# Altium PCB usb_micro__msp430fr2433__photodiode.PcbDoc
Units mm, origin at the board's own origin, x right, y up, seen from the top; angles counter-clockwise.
Board outline 56 x 30 mm, 2 copper layers (Top, Bottom), stack 0 mm thick; 25 components, 16 nets, 114 pads, 40 vias.
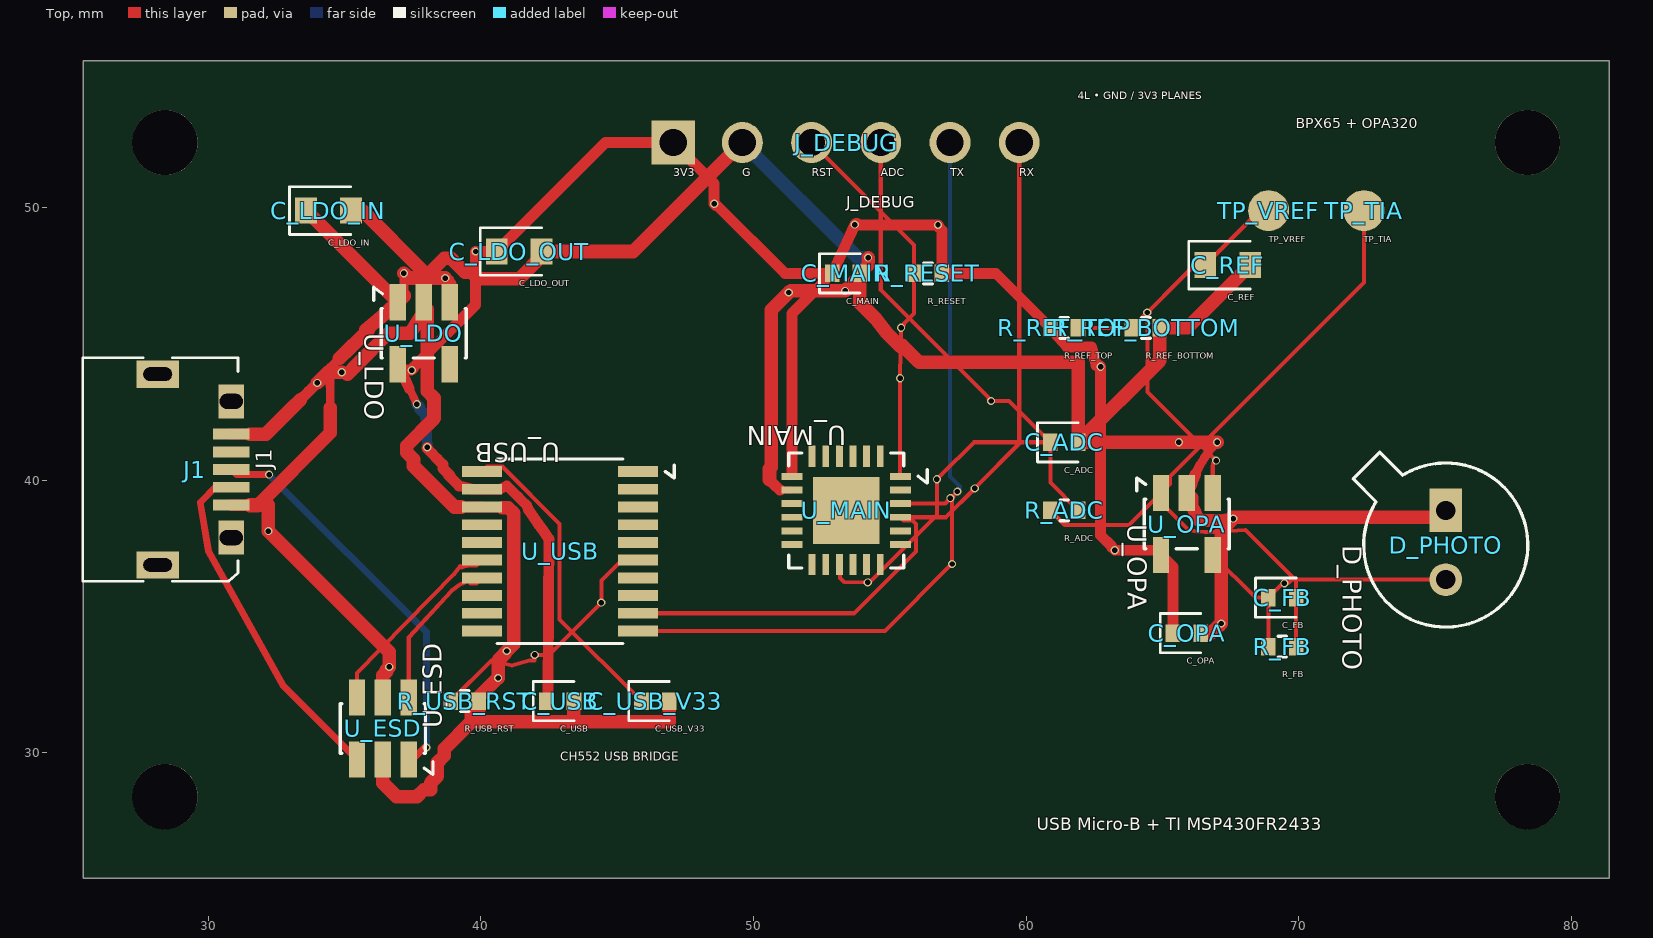
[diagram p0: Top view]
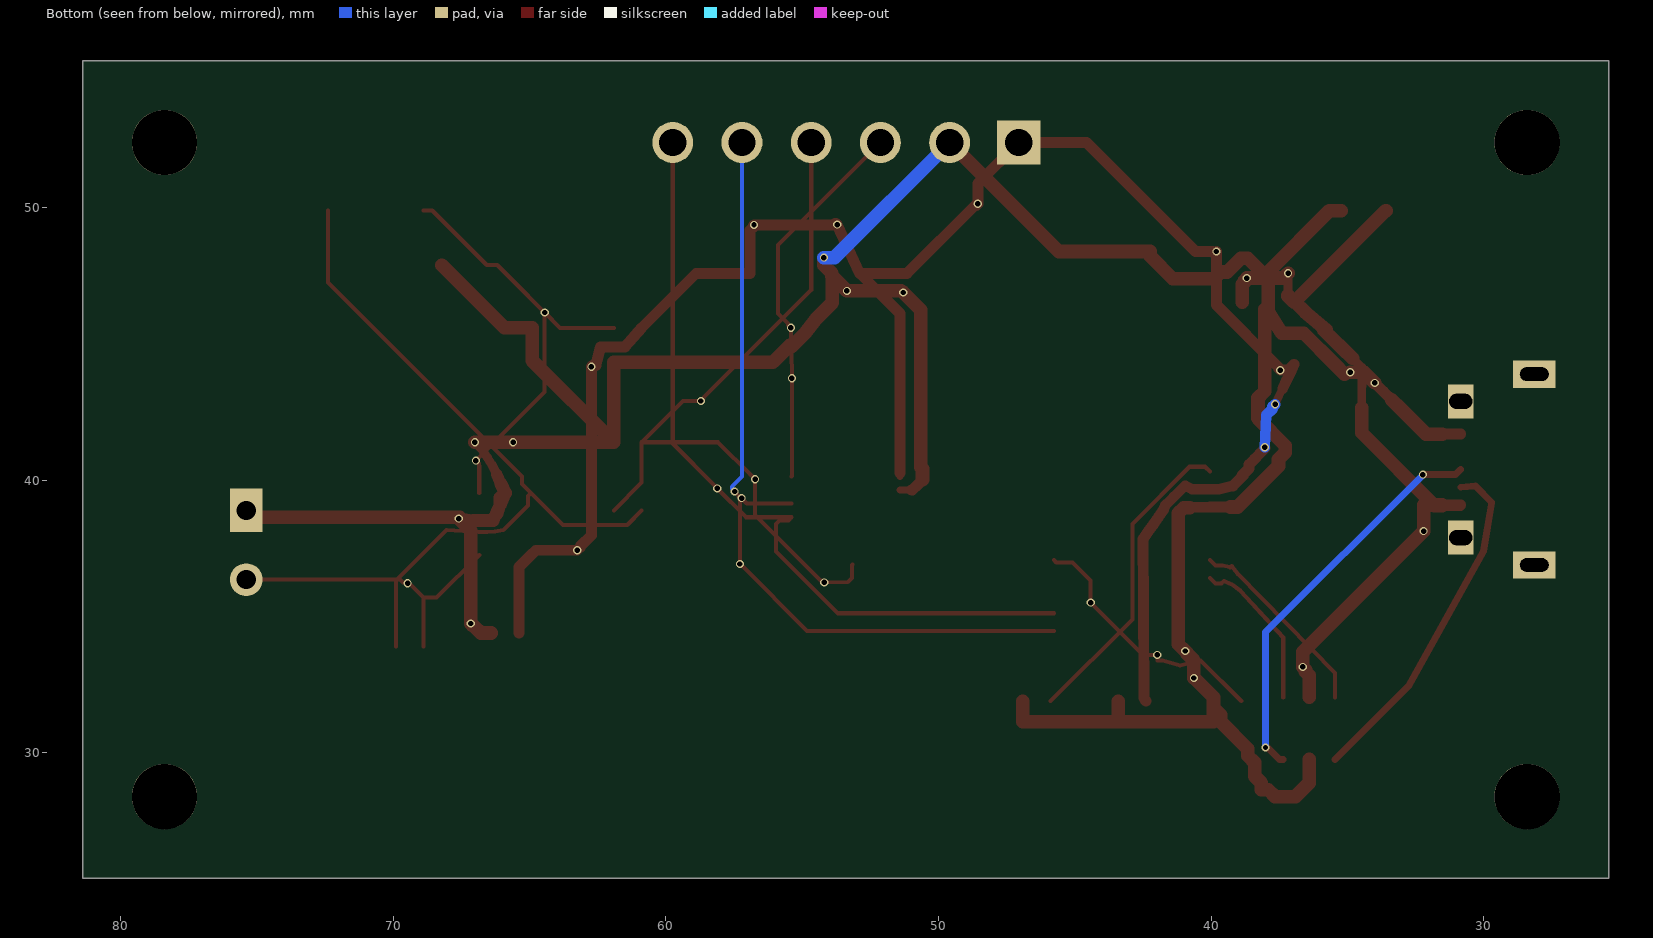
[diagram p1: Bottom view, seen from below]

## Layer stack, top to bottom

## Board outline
25.4,55.4 81.4,55.4 81.4,25.4 25.4,25.4

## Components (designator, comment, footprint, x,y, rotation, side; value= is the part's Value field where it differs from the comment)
C_ADC "" TSCIRCUIT-1.5600x0.6400mm 61.4,41.4 r0 top
C_FB "" TSCIRCUIT-1.5600x0.6400mm 69.4,35.7 r0 top
C_LDO_IN "" TSCIRCUIT-2.4500x0.9500mm 34.4,49.9 r0 top
C_LDO_OUT "" TSCIRCUIT-2.4500x0.9500mm 41.4,48.4 r0 top
C_MAIN "" TSCIRCUIT-1.5600x0.6400mm 53.4,47.6 r0 top
C_OPA "" TSCIRCUIT-1.5600x0.6400mm 65.9,34.4 r0 top
C_REF "" TSCIRCUIT-2.4500x0.9500mm 67.4,47.9 r0 top
C_USB "" TSCIRCUIT-1.5600x0.6400mm 42.9,31.9 r0 top
C_USB_V33 "" TSCIRCUIT-1.5600x0.6400mm 46.4,31.9 r0 top
D_PHOTO "" TSCIRCUIT-1.2000x3.9400mm 75.4,37.73 r270 top
J1 "" TSCIRCUIT-4.1500x8mm 29.437,40.4 r90 top
J_DEBUG "" TSCIRCUIT-14.2000x1.5000mm 53.4,52.4 r0 top
R_ADC "" TSCIRCUIT-1.5600x0.6400mm 61.4,38.9 r0 top
R_FB "" TSCIRCUIT-1.5600x0.6400mm 69.4,33.9 r0 top
R_REF_BOTTOM "" TSCIRCUIT-1.5600x0.6400mm 64.4,45.6 r0 top
R_REF_TOP "" TSCIRCUIT-1.5600x0.6400mm 61.4,45.6 r0 top
R_RESET "" TSCIRCUIT-1.5600x0.6400mm 56.4,47.6 r0 top
R_USB_RST "" TSCIRCUIT-1.5600x0.6400mm 39.4,31.9 r0 top
TP_TIA "" TSCIRCUIT-1.5000x1.5000mm 72.4,49.9 r0 top
TP_VREF "" TSCIRCUIT-1.5000x1.5000mm 68.9,49.9 r0 top
U_ESD "" TSCIRCUIT-2.5000x3.6000mm#1 36.4,30.9 r90 top
U_LDO "" TSCIRCUIT-2.5000x3.6000mm#2 37.9,45.4 r270 top
U_MAIN "" TSCIRCUIT-4.7500x4.7500mm 53.4,38.9 r180 top
U_OPA "" TSCIRCUIT-2.5000x3.6000mm#2 65.9,38.4 r270 top
U_USB "" TSCIRCUIT-7.2000x6.2500mm 42.9,37.4 r180 top

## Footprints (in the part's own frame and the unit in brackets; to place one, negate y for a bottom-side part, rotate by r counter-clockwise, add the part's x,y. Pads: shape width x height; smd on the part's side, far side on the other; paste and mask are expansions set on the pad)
TSCIRCUIT-1.2000x3.9400mm [mm]
  rect 1.6x1.2 hole 0.7: 1(-1.17,0)
  round 1.2 hole 0.7: 2(1.37,0)
  silkscreen extent -3.3,-3.4 3.11,3.01
TSCIRCUIT-1.5000x1.5000mm [mm]
  round 1.5 smd: 1(0,0)
TSCIRCUIT-1.5600x0.6400mm [mm]
  rect 0.54x0.64 smd: 1(-0.51,0) 2(0.51,0)
  silkscreen extent -0.98,-0.72 0.51,0.72
TSCIRCUIT-2.4500x0.9500mm [mm]
  rect 0.8x0.95 smd: 1(-0.825,0) 2(0.825,0)
  silkscreen extent -1.43,-0.87 0.82,0.87
TSCIRCUIT-2.5000x3.6000mm#1 [mm]
  rect 1.325x0.6 smd: 1(-1.137,-0.95) 2(-1.137,0) 3(-1.137,0.95) 4(1.138,0.95) 5(1.138,0) 6(1.138,-0.95)
  silkscreen extent -1.69,-1.84 0.91,1.56
TSCIRCUIT-2.5000x3.6000mm#2 [mm]
  rect 1.325x0.6 smd: 1(-1.137,-0.95) 2(-1.137,0) 3(-1.137,0.95) 4(1.138,0.95) 5(1.138,-0.95)
  silkscreen extent -1.69,-1.84 0.91,1.56
TSCIRCUIT-4.1500x8mm [mm]
  rect 0.4x1.35 smd: 1(-1.301,-1.4) 2(-0.65,-1.4) 3(0,-1.4) 4(0.65,-1.4) 5(1.3,-1.4)
  rect 1.25x0.95 hole 0.55 slot 0.85 at 90 deg: 6(2.5,-1.4) 7(-2.5,-1.4)
  rect 1x1.55 hole 0.5 slot 1.05 at 90 deg: 8(-3.5,1.3) 9(3.5,1.3)
  silkscreen extent -4.1,-1.65 4.1,4.05
TSCIRCUIT-4.7500x4.7500mm [mm]
  rect 0.775x0.25 smd: 1(-1.987,-1.25) 2(-1.987,-0.75) 3(-1.987,-0.25) 4(-1.987,0.25) 5(-1.987,0.75) 6(-1.987,1.25) 13(1.987,1.25) 14(1.987,0.75) 15(1.987,0.25) 16(1.987,-0.25) 17(1.987,-0.75) 18(1.987,-1.25)
  rect 0.25x0.775 smd: 7(-1.25,1.988) 8(-0.75,1.988) 9(-0.25,1.988) 10(0.25,1.988) 11(0.75,1.988) 12(1.25,1.988) 19(1.25,-1.987) 20(0.75,-1.987) 21(0.25,-1.987) 22(-0.25,-1.987) 23(-0.75,-1.987) 24(-1.25,-1.987)
  rect 2.45x2.45 smd: 25(0,0)
  silkscreen extent -2.97,-2.11 2.11,2.11
TSCIRCUIT-7.2000x6.2500mm [mm]
  rect 1.475x0.4 smd: 1(-2.862,-2.925) 2(-2.862,-2.275) 3(-2.862,-1.625) 4(-2.862,-0.975) 5(-2.862,-0.325) 6(-2.862,0.325) 7(-2.862,0.975) 8(-2.862,1.625) 9(-2.862,2.275) 10(-2.862,2.925) 11(2.863,2.925) 12(2.863,2.275) 13(2.863,1.625) 14(2.863,0.975) 15(2.863,0.325) 16(2.863,-0.325) 17(2.863,-0.975) 18(2.863,-1.625) 19(2.863,-2.275) 20(2.863,-2.925)
  silkscreen extent -4.19,-3.39 2.31,3.38
TSCIRCUIT-14.2000x1.5000mm [mm]
  rect 1.6x1.6 hole 1: 1(-6.35,0)
  round 1.5 hole 1: 2(-3.81,0) 3(-1.27,0) 4(1.27,0) 5(3.81,0) 6(6.35,0)

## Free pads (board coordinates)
  round 2.4 hole 2.4 unplated: NPTH-1(28.4,28.4) NPTH-2(78.4,52.4) NPTH-3(78.4,28.4) NPTH-4(28.4,52.4)

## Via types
v1: diameter 0.3, hole 0.2, Top to Bottom, 40 vias

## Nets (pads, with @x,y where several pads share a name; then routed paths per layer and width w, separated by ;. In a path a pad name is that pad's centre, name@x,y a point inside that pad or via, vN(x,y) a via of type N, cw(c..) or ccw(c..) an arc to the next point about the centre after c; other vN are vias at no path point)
ADC_IN: C_ADC.1 J_DEBUG.4 R_ADC.2 U_MAIN.10 | length 28.1
  Top w0.15: U_MAIN.10 53.173,36.889 53.173,36.424 53.328,36.268 v1(54.189,36.26) 54.248,36.327 54.329,36.327 56.728,38.725 v1(56.728,40.041) 56.887,40.2 58.087,41.4 C_ADC.1 ; J_DEBUG.4 54.67,46.984 58.618,43.036 58.618,43.013 v1(58.716,42.915) 59.375,42.915 C_ADC.1 ; R_ADC.2 60.89,39.92 C_ADC.1
GND: C_ADC.2 C_LDO_IN.2 C_LDO_OUT.2 C_MAIN.2 C_OPA.2 C_REF.2 C_USB.2 C_USB_V33.2 D_PHOTO.1 J1.5 J_DEBUG.2 R_REF_BOTTOM.2 R_USB_RST.2 U_ESD.2 U_LDO.2 U_MAIN.17 U_OPA.2 U_USB.18 | length 130.7
  Top w0.25: U_MAIN.17@51.025,39.65 U_MAIN.17
  Top w0.325: v1(34.891,43.969) 35.1,43.9 ; 66.369,40.556 66.552,40.841 66.734,41.125 v1(67.013,41.401)
  Top w0.35: 66.212,40.217 66.369,40.556
  Top w0.375: 50.962,39.65 51.025,39.65
  Top w0.4: J1.5 31.262,41.7 31.513,41.7 ; 33.364,42.952 33.677,43.265 v1(33.99,43.578) ; U_USB.18@39.3,39.025 U_USB.18 U_USB.18@40.775,39.001 ; 50.588,40.025 50.775,39.837 50.962,39.65
  Top w0.425: U_OPA.2@66.056,39.877 66.212,40.217
  Top w0.437: 66.744,38.541 67.072,38.541 67.336,38.57 v1(67.6,38.6) ; 66.9,38.525 67.291,38.541 v1@67.567,38.645
  Top w0.45: U_OPA.2@66.056,39.188 66.212,38.837 66.338,38.525 66.619,38.525 66.9,38.525 ; U_OPA.2@66.076,39.121 66.197,38.759 66.416,38.541 66.744,38.541
  Top w0.475: U_OPA.2@66.056,39.188 U_OPA.2 U_OPA.2@66.056,39.877
  Top w0.5: 31.513,41.7 31.687,41.7 32.112,41.7 32.425,42.013 32.738,42.326 33.051,42.639 33.364,42.952 ; v1(33.99,43.578) 34.381,43.969 v1(34.891,43.969) ; 35.1,43.9 35.45,44.25 36.6,45.4 37.4,45.4 37.9,46.186 U_LDO.2 ; C_LDO_IN.2 35.65,49.9 37.9,47.65 U_LDO.2 ; U_ESD.2 36.4,28.9 36.9,28.4 37.65,28.4 37.9,28.65 38.15,28.65 38.15,28.9 38.4,29.15 38.4,29.65 38.65,29.9 38.65,30.15 39.65,31.15 39.65,31.4 39.91,31.66 R_USB_RST.2 ; U_USB.18@39.3,39.025 39.025,39.025 37.525,40.525 37.525,40.775 37.275,41.025 37.275,41.275 38.275,42.275 38.275,43.025 38.025,43.275 38.025,46.275 37.9,46.4 U_LDO.2 ; 40.775,39.001 40.8,39 41,39 41.2,38.8 41.2,33.993 v1(40.948,33.741) 40.88,33.673 40.88,33.644 40.628,33.392 40.628,33.071 v1(40.628,32.75) 40.527,32.649 40.516,32.649 40.213,32.346 39.91,32.043 R_USB_RST.2 ; C_USB_V33.2 46.91,31.15 43.41,31.15 ; J_DEBUG.2 45.59,48.4 C_LDO_OUT.2 42.225,48.225 41.4,47.4 39.9,47.4 39.65,47.65 39.4,47.65 38.9,48.15 38.65,48.15 37.9,47.4 U_LDO.2 ; 50.588,40.025 50.588,40.421 50.651,40.485 50.651,46.255 v1(51.292,46.896) 51.342,46.946 51.365,46.946 51.374,46.955 51.87,46.955 52.367,46.955 52.863,46.955 v1(53.36,46.955) 53.91,47.505 C_MAIN.2 ; v1(54.206,48.177) 54.206,47.896 C_MAIN.2 ; U_OPA.2 66.076,39.362 U_OPA.2@66.076,39.121 ; C_OPA.2 66.788,34.4 67.051,34.663 67.078,34.663 v1(67.165,34.75) 67.165,38.165 v1(67.6,38.6) ; v1(67.013,41.401) 67.011,41.4 v1(65.609,41.4) 65.41,41.4 64.91,41.4 64.41,41.4 63.91,41.4 63.41,41.4 62.91,41.4 62.41,41.4 C_ADC.2 ; v1@67.567,38.645 68.041,38.645 68.514,38.645 68.988,38.645 69.461,38.645 69.935,38.645 70.409,38.645 70.882,38.645 71.356,38.645 71.83,38.645 72.303,38.645 72.777,38.645 73.25,38.645 73.724,38.645 74.198,38.645 74.671,38.645 75.145,38.645 D_PHOTO.1 ; C_REF.2 65.925,45.6 R_REF_BOTTOM.2 64.91,44.4 C_ADC.2 ; R_USB_RST.2 39.91,31.15 43.41,31.15 ; 43.41,31.15 C_USB.2 43.41,31.15 ; C_MAIN.2 53.904,47.243 53.898,46.886 53.893,46.528 54.204,46.215 54.516,45.902 54.9,45.4 55.4,44.9 55.452,44.962 55.763,44.649 56.075,44.336 56.555,44.34 61.91,44.34 C_ADC.2
  Bottom w0.5: J_DEBUG.2 53.813,48.177 v1(54.206,48.177)
MAIN_RESET: J_DEBUG.3 R_RESET.1 U_MAIN.1 | length 14
  Top w0.15: J_DEBUG.3 55.89,48.64 R_RESET.1 55.89,46.126 55.518,45.754 55.518,45.707 v1(55.416,45.605) 55.376,43.825 55.382,43.819 55.382,43.755 v1(55.376,43.749) 55.376,40.161 U_MAIN.1
PD_SUM: C_FB.1 D_PHOTO.2 R_FB.1 U_OPA.4 | length 11.3
  Top w0.15: U_OPA.4 68.412,35.7 C_FB.1 ; R_FB.1 C_FB.1 ; D_PHOTO.2 69.755,36.36 69.656,36.261 69.527,36.261 v1(69.478,36.23) 69.41,36.22 C_FB.1
TIA_OUT: C_FB.2 R_ADC.1 R_FB.2 TP_TIA.1 U_OPA.1 | length 27.1
  Top w0.15: R_ADC.1 61.42,38.37 63.782,38.37 U_OPA.1 ; R_FB.2 C_FB.2 69.91,36.328 68.056,38.182 66.868,38.102 66.571,38.103 66.273,38.128 65.969,38.182 65.065,39.085 65.065,39.422 U_OPA.1 ; TP_TIA.1 72.399,47.266 65.281,40.151 65.283,39.87 U_OPA.1
UART_MAIN_RX: J_DEBUG.6 U_MAIN.4 U_USB.9 | length 29.4
  Top w0.15: U_USB.9 53.69,35.125 55.965,37.393 55.965,38.405 55.836,38.528 55.51,38.528 U_MAIN.4 57.059,38.65 v1(58.118,39.709) 58.192,39.783 58.192,39.795 59.75,41.354 J_DEBUG.6
UART_MAIN_TX: J_DEBUG.5 U_MAIN.3 U_USB.10 | length 32.4
  Top w0.15: U_USB.10 54.82,34.475 57.254,36.909 57.26,36.909 v1(57.285,36.934) 57.285,39.371 57.329,39.415 57.329,39.444 v1(57.225,39.35) 57.035,39.15 ; v1(57.479,39.594) 57.035,39.15 ; 57.035,39.15 U_MAIN.3 57.035,39.15
  Bottom w0.15: J_DEBUG.5 57.21,40.143 57.583,39.77 57.583,39.698 v1(57.479,39.594)
USB_BRIDGE_RESET: R_USB_RST.1 U_USB.6 | length 9.6
  Top w0.15: R_USB_RST.1 40.385,33.395 41.136,33.214 41.771,33.395 41.97,33.395 v1(41.974,33.596) 42.491,33.596 44.384,35.489 v1(44.415,35.52) 44.415,36.327 45.079,36.991 45.679,36.991 U_USB.6
USB_BRIDGE_V33: C_USB_V33.1 U_USB.20 | length 11.5
  Top w0.15: U_USB.20 40.215,40.502 40.789,40.502 42.886,38.405 42.886,34.904 C_USB_V33.1
USB_DM_MCU: U_ESD.4 U_USB.15 | length 7.2
  Top w0.15: U_ESD.4 35.45,32.932 39.022,36.577 39.237,36.854 39.3,36.815 39.581,36.874 39.622,36.874 39.836,36.874 U_USB.15
USB_DM_PORT: J1.2 U_ESD.3 | length 12.7
  Top w0.25: J1.2 30.3,39.8 29.7,39.2 30,37.4 32.757,32.455 U_ESD.3
USB_DP_MCU: U_ESD.6 U_USB.14 | length 5.9
  Top w0.15: U_ESD.6 37.35,34.233 38.919,35.949 39.238,36.184 39.519,36.308 39.622,36.224 39.836,36.224 U_USB.14
USB_DP_PORT: J1.3 U_ESD.1 | length 14.7
  Top w0.25: J1.3 31.024,40.214 v1(32.223,40.214) ; U_ESD.1 37.481,29.763 37.919,30.2 v1(38,30.2)
  Bottom w0.25: v1(32.223,40.214) 32.247,40.19 38,34.437 v1(38,30.2)
VBUS5: C_LDO_IN.1 J1.1 U_ESD.5 U_LDO.1 U_LDO.3 | length 29.6
  Top w0.325: 34.471,42.661 34.466,43.155 34.462,43.649 34.457,44.143 34.808,44.485 ; v1(37.17,47.6) 37.173,47.193 U_LDO.1@37.176,46.786
  Top w0.35: v1(38.686,47.427) v1@38.783,47.33
  Top w0.4: 31.513,39.082 30.854,39.082 J1.1 31.513,39.099
  Top w0.5: 31.513,39.082 31.805,39.082 34.471,41.748 34.471,42.661 ; 31.513,39.099 32.197,39.099 v1(32.197,38.141) 32.274,38.064 36.634,33.704 v1(36.634,33.156) 36.534,33.056 36.534,32.982 36.4,32.848 U_ESD.5 ; C_LDO_IN.1 33.587,49.9 U_LDO.1 ; 34.808,44.485 35.159,44.828 35.51,45.17 35.861,45.512 35.775,45.525 36.562,46.197 36.913,46.539 U_LDO.1 ; v1(37.17,47.6) 37.343,47.427 v1(38.686,47.427) ; U_LDO.1@37.176,46.786 37.176,46.764 U_LDO.1 ; v1@38.783,47.33 38.783,47.26 38.85,47.193 38.85,46.865 U_LDO.3
VCC_3V3: C_LDO_OUT.1 C_MAIN.1 C_OPA.1 C_USB.1 J_DEBUG.1 R_REF_TOP.1 R_RESET.2 U_LDO.5 U_MAIN.18 U_OPA.5 U_USB.19 | length 73
  Top w0.25: U_MAIN.18 U_MAIN.18@51.413,40.275
  Top w0.3: 37.368,43.38 37.508,43.086 v1(37.647,42.792)
  Top w0.375: 40.95,39.8 41.325,39.438 41.5,39.262 41.675,39.088
  Top w0.387: U_USB.19@40.363,39.675 40.689,39.675 40.95,39.8 ; 41.675,39.088 41.739,38.929
  Top w0.4: 37.368,43.38 37.229,43.674 37.089,43.968 U_LDO.5 37.166,44.046 v1(37.457,44.046) 37.532,44.122 37.532,44.164 39.8,46.432 v1(39.8,48.4) 39.874,48.326 39.948,48.4 C_LDO_OUT.1 44.575,52.4 J_DEBUG.1 48.557,50.893 v1(48.557,50.154) 48.63,50.081 48.668,50.081 51.149,47.6 C_MAIN.1 ; v1(38.026,41.218) 38.012,41.191 38.012,41.183 38.21,40.981 38.408,40.78 38.607,40.578 38.607,40.434 38.86,40.181 38.8,40.2 39.2,39.8 39.702,39.675 U_USB.19 U_USB.19@40.363,39.675 ; 41.739,38.929 41.928,38.659 42.117,38.388 42.305,38.117 42.494,37.847 42.492,37.459 42.489,37.071 42.487,36.683 42.484,36.295 42.481,35.907 42.479,35.519 42.476,35.131 42.474,34.742 42.471,34.354 42.469,33.966 42.466,33.578 42.464,33.19 42.461,32.802 42.459,32.414 42.456,32.026 C_USB.1 ; 51.413,40.275 51.413,46.123 C_MAIN.1 ; C_OPA.1 65.39,36.822 U_OPA.5 64.773,37.439 v1(63.255,37.439) 63.135,37.559 63.135,37.59 62.737,37.988 v1(62.737,44.174) 62.69,44.221 62.569,44.221 62.4,44.9 61.5,44.9 R_REF_TOP.1 58.89,47.6 R_RESET.2 56.91,49.181 56.79,49.3 56.79,49.357 v1(56.769,49.378) 53.838,49.378 53.79,49.426 53.756,49.426 v1(53.716,49.386) C_MAIN.1
  Bottom w0.4: v1(37.647,42.792) 37.748,42.707 37.748,42.623 37.974,42.397 37.991,42.004 38.009,41.611 v1(38.026,41.218)
VREF_0V5: C_REF.1 R_REF_BOTTOM.1 R_REF_TOP.2 TP_VREF.1 U_OPA.3 | length 17.3
  Top w0.15: R_REF_TOP.2 R_REF_BOTTOM.1 ; U_OPA.3 66.85,40.522 66.861,40.533 66.861,40.618 v1(66.971,40.728) 64.45,43.249 64.45,45.96 64.45,46.159 v1(64.447,46.162) 64.447,46.157 R_REF_BOTTOM.1 ; TP_VREF.1 68.575,49.9 C_REF.1 66.19,47.9 R_REF_BOTTOM.1
pads on no net: J1.4 J1.6 J1.7 J1.8 J1.9 U_LDO.4 U_MAIN.2 U_MAIN.5 U_MAIN.6 U_MAIN.7 U_MAIN.8 U_MAIN.9 U_MAIN.11 U_MAIN.12 U_MAIN.13 U_MAIN.14 U_MAIN.15 U_MAIN.16 U_MAIN.19 U_MAIN.20 U_MAIN.21 U_MAIN.22 U_MAIN.23 U_MAIN.24 U_MAIN.25 U_USB.1 U_USB.2 U_USB.3 U_USB.4 U_USB.5 U_USB.7 U_USB.8 U_USB.11 U_USB.12 U_USB.13 U_USB.16 U_USB.17

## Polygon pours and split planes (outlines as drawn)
GND on Mid1 (solid): 81.1,55.1 25.7,55.1 25.7,25.7 81.1,25.7
VCC_3V3 on Mid2 (solid): 81.1,55.1 25.7,55.1 25.7,25.7 81.1,25.7

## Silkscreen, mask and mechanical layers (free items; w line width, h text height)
Top Overlay:
  text "4L • GND / 3V3 PLANES" at 61.9,53.9 h0.48
  text "BPX65 + OPA320" at 69.9,52.8 h0.65
  text "CH552 USB BRIDGE" at 42.9,29.6 h0.55
  text "USB Micro-B + TI MSP430FR2433" at 60.4,27 h0.78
